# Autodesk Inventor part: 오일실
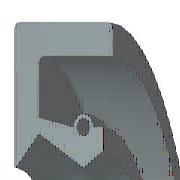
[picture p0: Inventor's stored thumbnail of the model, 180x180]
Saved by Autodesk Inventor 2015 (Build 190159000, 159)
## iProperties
IsCustomPart: 0
Created: 2009-02
Part Number: 오일실
Material: 고무
Description: 오일-실
Document SubType Name: Modeling
Standard: KS B 2804
Designer: KYOUNG IL JANG
Standards Organization: KS
Language: ko-KR
Size Designation: D - 20 32 8
Categories: <MemberInstance><Categories><Category DisplayName="샤프트 부품" InternalName="7f7aeb1f-a693-4053-b835-cee3144e0d98" Mnemonic="SHFT"><Category DisplayName="실링" Intern
Density: 0.93 g/cm^3
Mass: 2.19344 g
Surface Area: 31.4782 cm^2
Volume: 2.35853 cm^3
Appearance: 고무 - 검은색 - 버전 1.1
Author: KYOUNG IL JANG
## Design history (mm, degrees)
revolve "본체" stored, may be unused: angle "d17" = 90 deg
revolve "스프링1" stored, may be unused: angle "d18" = 90 deg
body "Solid1"
sketch "스케치1"
  geometry: L1 (0, 16)-(8, 16); L2 (8, 14.25)-(1.75, 14.25); L3 (1.75, 11.75)-(4.9, 10); L4 (4.9, 10)-(0, 10); L5 (0, 0)-(9.586, 0) reference; L6 (4.9, 10)-(6.3, 10.875); L7 (0, 18)-(0, -3) reference; L8 (-1.941, 0)-(11.507, 0) reference; L9 (4.2, 12.1)-(1.75, 12.71); L10 (1.75, 12.71)-(1.75, 14.25); L11 (0, 16)-(0, 10.088); L12 (4.9, 10)-(0, 10); L13 (1.75, 11.75)-(0.152, 10.028); L14 (8, 16)-(8, 14.25); L15 (5.6, 12.1)-(6.3, 12.1); L16 (6.3, 12.1)-(6.3, 10.875); C1 r 0.455 at (4.9, 12.1); A1 r 0.7 centre (4.9, 12.1) between (5.6, 12.1) and (4.2, 12.1); A2 r 0.088 centre (0.088, 10.088) between (0, 10.088) and (0.152, 10.028); 1 further point
  constraints: 28 end point, 5 horizontal alignment, 5 point on line, 4 point on circle, 4 vertical alignment, 3 centre point, 3 tangent, 2 collinear, 2 horizontal, 2 perpendicular, 1 coincident, 1 parallel
  dimensions: "d0" = 32 diameter of L1 L5 (= SD2); "d1" = 1.75 distance of L1.end L2.start (= SD); "d2" = 0.91 diameter of C1 (= SPDI); "d3" = 1.4 diameter of A1 (= SPDA); "d4" = 20 diameter of L3.end L5 (= NND); "d5" = 23.5 diameter of L3.start L5 (= TKDM); "d7" = 25.42 diameter of L9.end L5 (= TKDM + 0.24 x SWDT); "d8" = 1.75 distance between parallel lines of L11 L10 (= SD); "d9" = 4.9 distance from line of L11 C1.centre (= SPDST); "d10" = 24.2 diameter of C1.centre L5 (= HLDM); "d11" = 0.0875 radius of A2 (= 0.25 x LAB); "d12" = 6.3 distance between parallel lines of L11 L16 (= SDI); "d13" = 21.75 diameter of L6.end L5 (= ABDM); "d14" = 8 distance from line of L11 L1.end (= SWDT)
fillet "모깎기1" dims "d6" = 0.3 (= RR)
other parameters: "SD2" = 32 [user parameter; used in 1 equation term], "SWDT" = 8 [user parameter; used in 2 equation terms], "RR" = 0.3 [user parameter; used in 1 equation term], "SD" = 1.75 [user parameter; used in 2 equation terms], "NND" = 20 [user parameter; used in 1 equation term], "SPDA" = 1.4 [user parameter; used in 1 equation term], "SPDI" = 0.91 [user parameter; used in 1 equation term], "TKDM" = 23.5 [user parameter; used in 2 equation terms], "HLDM" = 24.2 [user parameter; used in 1 equation term], "ABDM" = 21.75 [user parameter; used in 1 equation term], "SDI" = 6.3 [user parameter; used in 1 equation term], "SPDST" = 4.9 [user parameter; used in 1 equation term], "LAB" = 0.35 [user parameter; used in 1 equation term], "d15" = 0, "d16" = 0, "d19" = 0
